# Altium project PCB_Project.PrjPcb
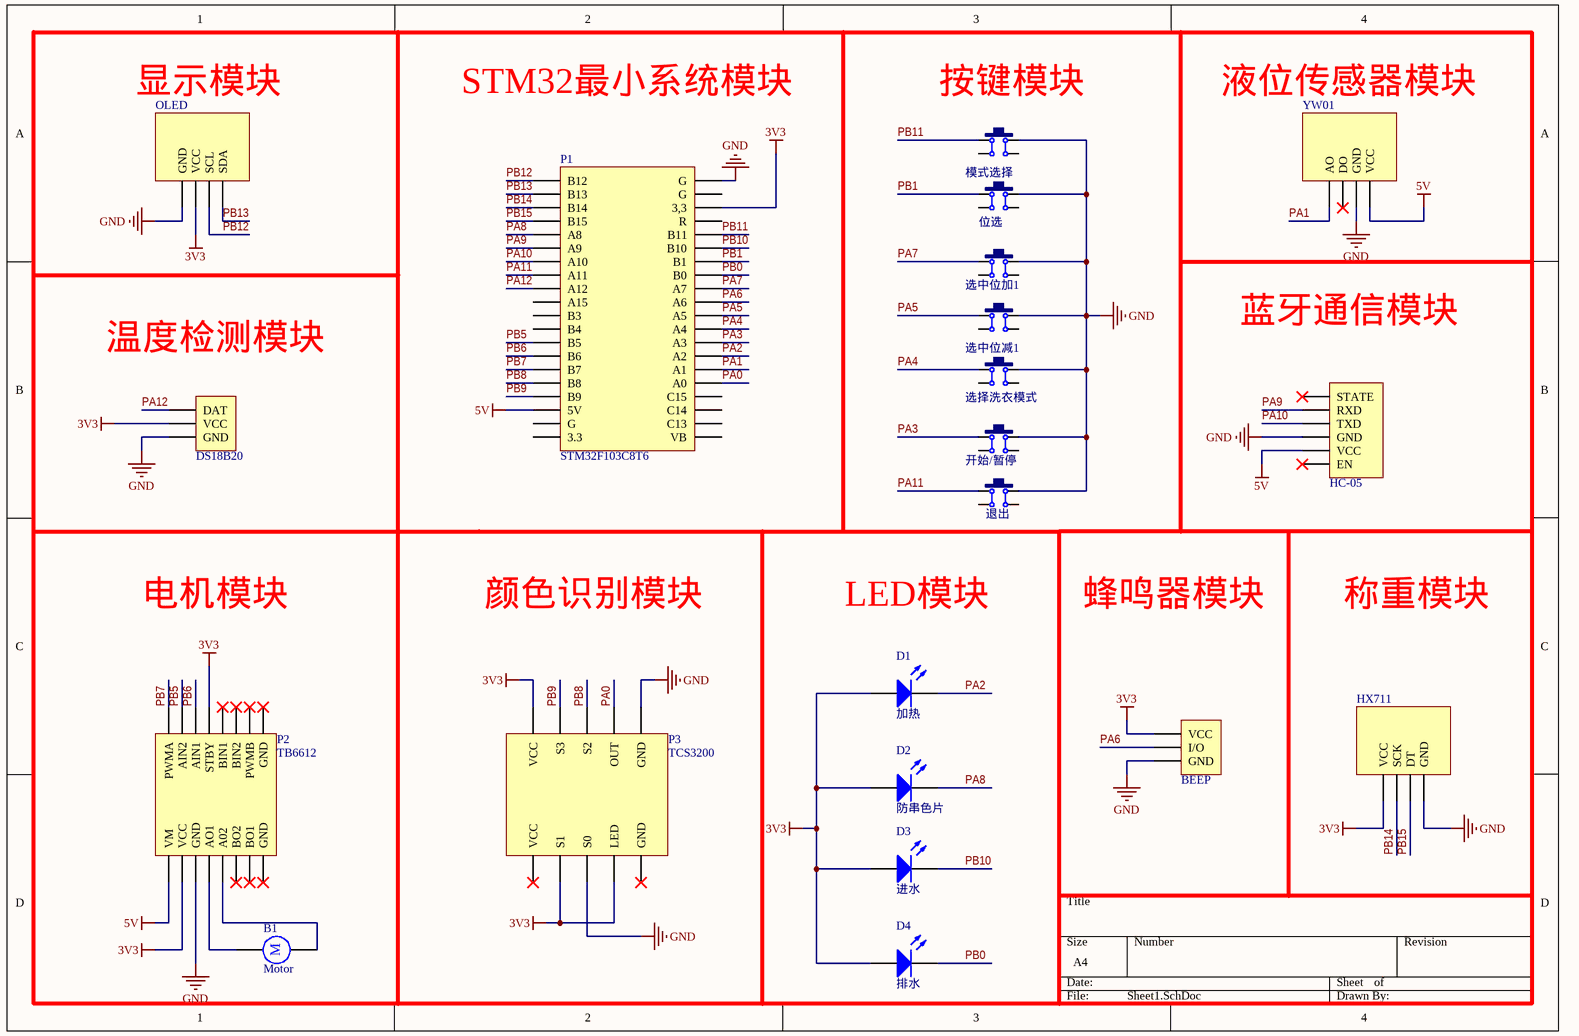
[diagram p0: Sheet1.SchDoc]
1 sheet, 21 parts. Net scope: global (net labels, ports and power ports of the same name join across sheets).
Board file: PCB1.PcbDoc

## Sheet Sheet1.SchDoc
size A4

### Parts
B1  Motor  [HDR2.54-LI-2P]
BEEP  BEEP  [HDR2.54-M-LI-3P]  (value not drawn)
D1  加热  [LED 5MM-R]
D2  防串色片  [LED 5MM-R]
D3  进水  [LED 5MM-R]
D4  排水  [LED 5MM-R]
DS18B20  ?  [HDR2.54-M-LI-3P]  (value not drawn)
HC-05  HC-05  [HDR2.54-M-LI-6P]  (value not drawn)
HX711  HX711  [HDR2.54-M-LI-4P]
OLED  OLED0.96  [HDR2.54-M-LI-4P]  (value not drawn)
P1  STM32F103C8T6  [DIP40-600_MH]
P2  TB6612  [HDR2.54-M-LI-8*2P]
P3  TCS3200  [HDR2.54-M-LI-5*2P]
YW01  YW01  [HDR2.54-M-LI-4P]
位选  TSW DIP-6x6  [TSW DIP-6*6*6]  (value not drawn)
开始/暂停  TSW DIP-6x6  [TSW DIP-6*6*6]  (value not drawn)
模式选择  TSW DIP-6x6  [TSW DIP-6*6*6]  (value not drawn)
退出  TSW DIP-6x6  [TSW DIP-6*6*6]  (value not drawn)
选中位减1  TSW DIP-6x6  [TSW DIP-6*6*6]  (value not drawn)
选中位加1  TSW DIP-6x6  [TSW DIP-6*6*6]  (value not drawn)
选择洗衣模式  TSW DIP-6x6  [TSW DIP-6*6*6]  (value not drawn)

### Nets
3V3: BEEP.1(VCC) D1.1(A) D2.1(A) D3.1(A) D4.1(A) DS18B20.2(VCC) HX711.1(VCC) OLED.2(VCC) P1.38(3,3) P2.2(VCC) P2.12(STBY) P3.2(S1) P3.4(LED) P3.6(VCC)
5V: HC-05.5(VCC) P1.18(5V) P2.1(VM) YW01.4(VCC)
GND: BEEP.3(GND) DS18B20.3(GND) HC-05.4(GND) HX711.4(GND) OLED.1(GND) P1.40(G) P2.3(GND) P3.3(S0) P3.10(GND) YW01.3(GND) 位选.2 开始/暂停.2 模式选择.2 退出.2 选中位减1.2 选中位加1.2 选择洗衣模式.2
PA0: P1.25(A0) P3.9(OUT)
PA1: P1.26(A1) YW01.1(AO)
PA2: D1.2(K) P1.27(A2)
PA3: P1.28(A3) 开始/暂停.1
PA4: P1.29(A4) 选择洗衣模式.1
PA5: P1.30(A5) 选中位减1.1
PA6: BEEP.2(I/O) P1.31(A6)
PA7: P1.32(A7) 选中位加1.1
PA8: D2.2(K) P1.5(A8)
PA9: HC-05.2(RXD) P1.6(A9)
PA10: HC-05.3(TXD) P1.7(A10)
PA11: P1.8(A11) 退出.1
PA12: DS18B20.1(DAT) P1.9(A12)
PB0: D4.2(K) P1.33(B0)
PB1: P1.34(B1) 位选.1
PB5: P1.13(B5) P2.10(AIN2)
PB6: P1.14(B6) P2.11(AIN1)
PB7: P1.15(B7) P2.9(PWMA)
PB8: P1.16(B8) P3.8(S2)
PB9: P1.17(B9) P3.7(S3)
PB10: D3.2(K) P1.35(B10)
PB11: P1.36(B11) 模式选择.1
PB12: OLED.3(SCL) P1.1(B12)
PB13: OLED.4(SDA) P1.2(B13)
PB14: HX711.2(SCK) P1.3(B14)
PB15: HX711.3(DT) P1.4(B15)
NetB1_1: B1.1 P2.4(AO1)
NetB1_2: B1.2 P2.5(A02)

Not connected (* = marked no-connect by the designer): HC-05 1(STATE)* 6(EN)*; P1 10(A15) 11(B3) 12(B4) 19(G) 20(3.3) 21(VB) 22(C13) 23(C14) 24(C15) 37(R) 39(G); P2 6(BO2)* 7(BO1)* 8(GND)* 13(BIN1)* 14(BIN2)* 15(PWMB)* 16(GND)*; P3 1(VCC)* 5(GND)*; YW01 2(DO)*; 位选 3 4; 开始/暂停 3 4; 模式选择 3 4; 退出 3 4; 选中位减1 3 4; 选中位加1 3 4; 选择洗衣模式 3 4

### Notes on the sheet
- 显示模块
- STM32最小系统模块
- (near 模式选择) 按键模块
- 液位传感器模块
- 温度检测模块
- 蓝牙通信模块
- 电机模块
- 颜色识别模块
- LED模块
- 蜂鸣器模块
- 称重模块

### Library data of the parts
B1 = Motor: Motor, General Kind
BEEP = BEEP: BEEP, 3-Pin
D1-D4 = LED: Typical INFRARED GaAs LED
DS18B20 = DS18B20: DS18B20, 3-Pin
HC-05 = HC-05: HC-05, 6-Pin
HX711 = HX711: HX711,4-Pin
OLED = OLED: OLED0.96,4-Pin
P1 = STM32F103C8T6: 最小系统板
P2 = TB66612: TB66612,16-Pin
P3 = PCS3200: PCS3200, 10-Pin, Dual row
YW01 = YW01: YW01,4-Pin
位选 开始/暂停 模式选择 退出 选中位减1 选中位加1 选择洗衣模式 = TSW DIP-6x6: 直插6*6*5轻触开关; BOM名称: 直插12x12轻触开关; 版权归属: 封装库来自淘宝 ID：黄晶宝石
